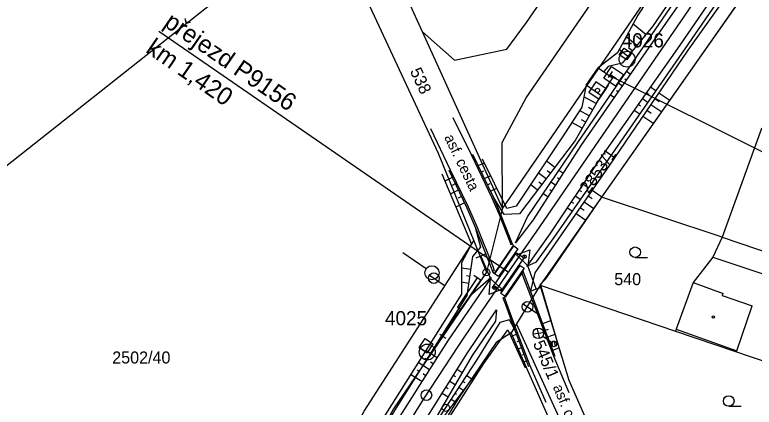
# Model space of a CAD drawing. Extents: x -558358 to -557517, y -1073786 to -1073189.
# Drawn here: x -558303.9 to -558199.4, y -1073559.5 to -1073504 of the extents above; entities that cross this region are included whole.
import ezdxf

# ---------------------------------------------------------------- set-up
doc = ezdxf.new("R2010")
doc.units = 0
for name, color, linetype in [('Body', 7, 'Continuous'), ('bubliny', 7, 'Continuous'), ('Hranice parcel', 7, 'Continuous'), ('Kolej', 7, 'Continuous'), ('Lomové body_cisla', 7, 'Continuous'), ('Lomové body_krizky', 7, 'Continuous'), ('nové prvky ZZ', 7, 'Continuous'), ('Návěst místo trati', 7, 'Continuous'), ('Návěst ostatní', 7, 'Continuous'), ('Parcelní čísla', 7, 'Continuous'), ('Plot - zábradlí', 7, 'Continuous'), ('Přejezd - štěrkové lože', 7, 'Continuous'), ('Sdělovací objekt', 7, 'Continuous'), ('Sonda - šrafa - vrstevnice', 7, 'Continuous'), ('Svazek obcí údolí Desné', 7, 'Continuous'), ('Svršek součást', 7, 'Continuous'), ('Vedení nerozlišené', 7, 'Continuous'), ('Vnitřní kresba', 7, 'Continuous'), ('Vrstva 1', 7, 'Continuous'), ('Vrstva 28', 7, 'Continuous'), ('Vrstva 60', 7, 'Continuous'), ('Značky budov', 7, 'Continuous'), ('Značky kultur', 7, 'Continuous'), ('ŽKN drážní hranice', 7, 'Continuous')]:
    doc.layers.add(name, color=color, linetype=linetype)

msp = doc.modelspace()

# ---------------------------------------------------------------- linework, layer by layer
at = {"layer": 'Body'}
for p, q in [((-558217.8, -1073508.74), (-558216.76, -1073509.48)), ((-558217.4, -1073510.42), (-558218.48, -1073509.68)), ((-558246.72, -1073551.05), (-558245.6, -1073551.8))]:
    msp.add_line(p, q, dxfattribs=at)
for points in [[(-558216.76, -1073509.48), (-558217.4, -1073510.42), (-558218.48, -1073509.68), (-558217.8, -1073508.74), (-558216.76, -1073509.48)], [(-558218.48, -1073509.68), (-558218.48, -1073509.68), (-558217.8, -1073508.74), (-558217.8, -1073508.74)], [(-558244.79, -1073550.55), (-558245.6, -1073551.8), (-558246.72, -1073551.05), (-558245.88, -1073549.79), (-558244.79, -1073550.55)], [(-558246.72, -1073551.05), (-558246.72, -1073551.05), (-558245.88, -1073549.79)]]:
    msp.add_lwpolyline(points, dxfattribs=at)
at = {"layer": 'bubliny'}
for points in [[(-558241.97, -1073518.56), (-558239.36, -1073523.89), (-558236.46, -1073529.9), (-558235.46, -1073532.27), (-558233.99, -1073535.97), (-558233.78, -1073536.52), (-558233.57, -1073536.45), (-558233.47, -1073536.63), (-558236.17, -1073540.59), (-558236.37, -1073540.25)], [(-558245.14, -1073520.13), (-558242.35, -1073525.93), (-558239.8, -1073531.2), (-558238.6, -1073533.96), (-558236.31, -1073539.72), (-558236.16, -1073540.16)], [(-558233.57, -1073536.45), (-558235.25, -1073532.18), (-558236.26, -1073529.8), (-558239.16, -1073523.77)], [(-558242.57, -1073526.01), (-558240.01, -1073531.3), (-558238.82, -1073534.05), (-558236.37, -1073540.25), (-558236.16, -1073540.16)], [(-558227.51, -1073552.32), (-558229.58, -1073546.84), (-558231, -1073543.03), (-558232.06, -1073540.27), (-558232.25, -1073540.54), (-558234.54, -1073543.87), (-558234.71, -1073543.93), (-558234.92, -1073544.01), (-558234.56, -1073544.97), (-558233.31, -1073548.35), (-558231.29, -1073553.74)], [(-558232.25, -1073540.54), (-558231.98, -1073541.2), (-558229.8, -1073546.93), (-558227.73, -1073552.39), (-558225.6, -1073557.4)], [(-558228.82, -1073558.84), (-558231.07, -1073553.66), (-558233.11, -1073548.21), (-558234.34, -1073544.89), (-558234.71, -1073543.93)]]:
    msp.add_lwpolyline(points, dxfattribs=at)
at = {"layer": 'Hranice parcel'}
for p, q in [((-558325.69, -1073541.72), (-558259.89, -1073489.61)), ((-558246.29, -1073506.44), (-558252.58, -1073492.61)), ((-558234.96, -1073531.36), (-558246.29, -1073506.44)), ((-558234.96, -1073531.36), (-558235.03, -1073522.1)), ((-558203.93, -1073535.45), (-558220.99, -1073529.81)), ((-558229.66, -1073542.22), (-558210.55, -1073548.74)), ((-558218.9, -1073578.68), (-558232.98, -1073547.69)), ((-558220.27, -1073579.28), (-558233.76, -1073548.97)), ((-558210.55, -1073548.74), (-558179.99, -1073559.12))]:
    msp.add_line(p, q, dxfattribs=at)
for points in [[(-558246.29, -1073506.44), (-558241.75, -1073510.46), (-558234.37, -1073508.88), (-558231.59, -1073505.15), (-558202.26, -1073462.53)], [(-558235.03, -1073522.1), (-558231.61, -1073515.78), (-558197.28, -1073465.89)], [(-558259.89, -1073489.61), (-558244.04, -1073523.6), (-558239.03, -1073535.96)], [(-558195.03, -1073520.62), (-558198.39, -1073520.09), (-558203.93, -1073535.45)], [(-558203.93, -1073535.45), (-558205.25, -1073538.29), (-558208.03, -1073541.86), (-558210.44, -1073548.45), (-558210.55, -1073548.74)], [(-558203.93, -1073535.45), (-558199.11, -1073537.11), (-558193.35, -1073539.1), (-558189.69, -1073540.36), (-558187.24, -1073541.19), (-558177.37, -1073544.49)], [(-558219.67, -1073569.09), (-558225.55, -1073555.71), (-558229.66, -1073542.22)]]:
    msp.add_lwpolyline(points, dxfattribs=at)
at = {"layer": 'Kolej'}
for points in [[(-558222.5, -1073523.52), (-558211.35, -1073507.26), (-558189.16, -1073474.89), (-558177.86, -1073458.42), (-558166.63, -1073442.09)], [(-558250.41, -1073565.28), (-558246.06, -1073558.3), (-558241.22, -1073550.9), (-558238.65, -1073547.06), (-558235.71, -1073542.74), (-558232.47, -1073538.02), (-558229.71, -1073534.01), (-558222.5, -1073523.52)]]:
    msp.add_lwpolyline(points, dxfattribs=at)
at = {"layer": 'Lomové body_cisla'}
for p, q in [((-558229.71, -1073549.76), (-558230.08, -1073548.32)), ((-558230.65, -1073549.14), (-558229.17, -1073548.94)), ((-558229.29, -1073549.47), (-558228.05, -1073550.31)), ((-558227.88, -1073550.9), (-558228, -1073550.25)), ((-558227.48, -1073550.85), (-558227.61, -1073550.16))]:
    msp.add_line(p, q, dxfattribs=at)
msp.add_lwpolyline([(-558221.47, -1073511.54), (-558219.41, -1073512.95), (-558221.09, -1073515.43), (-558223.16, -1073514)], close=True, dxfattribs=at)
for centre, radius in [((-558229.91, -1073549.05), 0.749), ((-558227.72, -1073550.54), 0.4), ((-558227.72, -1073550.54), 0.4)]:
    msp.add_circle(centre, radius, dxfattribs=at)
at = {"layer": 'Lomové body_krizky'}
msp.add_line((-558247.8, -1073566.83), (-558237.59, -1073553.32), dxfattribs=at)
for points in [[(-558160.27, -1073422.61), (-558170.92, -1073439.28), (-558182.07, -1073455.63), (-558193.45, -1073472.04), (-558204.95, -1073487.53), (-558215.83, -1073504.11), (-558218.74, -1073509.41), (-558221.47, -1073511.54)], [(-558158.61, -1073423.97), (-558169.15, -1073440.42), (-558180.26, -1073456.88), (-558191.27, -1073472.78), (-558202.46, -1073489.11), (-558213.8, -1073505.71), (-558218.06, -1073510.9), (-558220.02, -1073511.36), (-558220.66, -1073512.06)], [(-558152.7, -1073428.17), (-558163.49, -1073444.26), (-558174.92, -1073460.4), (-558186.51, -1073476.58), (-558197.24, -1073492.86), (-558208.77, -1073509.05), (-558219.85, -1073525.27), (-558227.1, -1073535.75), (-558230.39, -1073540.52), (-558231, -1073543.03)], [(-558223.16, -1073514), (-558223.75, -1073517.08), (-558226.14, -1073520.73), (-558233.06, -1073531.07), (-558234.34, -1073531.39), (-558237.78, -1073524.45)], [(-558221.09, -1073515.43), (-558224.69, -1073521.8), (-558232.56, -1073532.17), (-558234.74, -1073532.28), (-558236.26, -1073529.8)], [(-558243.55, -1073526.52), (-558241.09, -1073532.31), (-558239.34, -1073536.46), (-558240.77, -1073539.1), (-558240.78, -1073543.51), (-558244.12, -1073548.8), (-558253.49, -1073563.6), (-558259.69, -1073574.14), (-558265.34, -1073584.72), (-558270.8, -1073595.81), (-558275.48, -1073606.81), (-558278.77, -1073618.5)], [(-558238.82, -1073534.05), (-558238.07, -1073536.86), (-558239.2, -1073538.21), (-558240, -1073543.71), (-558243.46, -1073549.18), (-558252.76, -1073564.02), (-558258.92, -1073574.47), (-558264.72, -1073585.09), (-558269.64, -1073596.42), (-558274.5, -1073607.3), (-558278.77, -1073618.5)], [(-558233.31, -1073548.35), (-558233.96, -1073547.13), (-558235.35, -1073547.54), (-558238.57, -1073552.68), (-558247.8, -1073566.83)]]:
    msp.add_lwpolyline(points, dxfattribs=at)
at = {"layer": 'nové prvky ZZ'}
msp.add_line((-558233.36, -1073548.08), (-558233.26, -1073548.14), dxfattribs=at)
at = {"layer": 'Návěst místo trati'}
for p, q in [((-558243.83, -1073549.16), (-558242.99, -1073549.72)), ((-558243.69, -1073549.86), (-558243.14, -1073549.02))]:
    msp.add_line(p, q, dxfattribs=at)
for centre, radius in [((-558245.72, -1073557.78), 0.75), ((-558242.97, -1073559.57), 0.5), ((-558242.97, -1073559.57), 0.5)]:
    msp.add_circle(centre, radius, dxfattribs=at)
at = {"layer": 'Návěst ostatní'}
for p, q in [((-558238.54, -1073541.21), (-558241.35, -1073545.35)), ((-558238.54, -1073541.21), (-558239.04, -1073540.87)), ((-558238.05, -1073541.55), (-558238.54, -1073541.21)), ((-558240.85, -1073545.68), (-558238.05, -1073541.55)), ((-558241.35, -1073545.35), (-558240.85, -1073545.68))]:
    msp.add_line(p, q, dxfattribs=at)
at = {"layer": 'Plot - zábradlí'}
for points in [[(-558226.6, -1073552.39), (-558229.62, -1073542.12), (-558228.84, -1073541.34), (-558220.94, -1073529.81), (-558210.66, -1073515.21), (-558195.56, -1073493.62), (-558184.31, -1073477.57), (-558177.73, -1073468.27), (-558161.67, -1073445.55), (-558150.68, -1073429.95)], [(-558267.89, -1073660.39), (-558276.96, -1073659.75), (-558281.76, -1073647.44), (-558277.17, -1073632.83), (-558274.66, -1073624.85), (-558270.86, -1073615.23), (-558262.75, -1073596.69), (-558258.8, -1073588.16), (-558252.1, -1073576.95), (-558245.86, -1073566.23), (-558237.59, -1073553.32), (-558234.22, -1073548.55), (-558231.78, -1073553.91)]]:
    msp.add_lwpolyline(points, dxfattribs=at)
at = {"layer": 'Přejezd - štěrkové lože'}
for p, q in [((-558283.53, -1073506.38), (-558234.1, -1073540.39)), ((-558216.93, -1073512.45), (-558217.46, -1073512.08)), ((-558218.07, -1073514.09), (-558218.59, -1073513.73)), ((-558217.5, -1073513.27), (-558217.71, -1073513.12)), ((-558218.64, -1073514.91), (-558218.85, -1073514.77)), ((-558214.64, -1073515.05), (-558214.32, -1073515.28)), ((-558214.06, -1073514.23), (-558213.26, -1073514.8)), ((-558219.21, -1073515.73), (-558219.72, -1073515.38)), ((-558215.21, -1073515.87), (-558214.4, -1073516.44)), ((-558215.79, -1073516.68), (-558215.46, -1073516.92)), ((-558216.37, -1073517.5), (-558215.54, -1073518.08)), ((-558226.43, -1073526.41), (-558226.99, -1073526.05)), ((-558226.96, -1073527.26), (-558227.2, -1073527.1)), ((-558227.5, -1073528.1), (-558228.12, -1073527.7)), ((-558223.59, -1073527.97), (-558222.78, -1073528.51)), ((-558228.58, -1073529.78), (-558229.24, -1073529.36)), ((-558228.04, -1073528.94), (-558228.3, -1073528.78)), ((-558224.7, -1073529.63), (-558223.92, -1073530.15)), ((-558224.15, -1073528.8), (-558223.83, -1073529.01)), ((-558225.25, -1073530.46), (-558224.95, -1073530.67)), ((-558225.81, -1073531.3), (-558225.07, -1073531.79)), ((-558233.4, -1073536.68), (-558236.1, -1073540.62)), ((-558237.3, -1073537.83), (-558238.73, -1073538.43)), ((-558231.97, -1073538.44), (-558231.75, -1073538)), ((-558234.61, -1073543.82), (-558231.9, -1073539.88)), ((-558236.03, -1073542.36), (-558236.22, -1073542.81)), ((-558230.94, -1073543.03), (-558229.47, -1073542.51)), ((-558244.21, -1073552.5), (-558245.16, -1073551.89)), ((-558245.29, -1073554.19), (-558246.22, -1073553.59)), ((-558244.75, -1073553.34), (-558245.12, -1073553.1)), ((-558245.83, -1073555.03), (-558246.2, -1073554.79)), ((-558241.36, -1073554.11), (-558240.65, -1073554.56)), ((-558246.37, -1073555.87), (-558247.29, -1073555.28)), ((-558242.42, -1073555.81), (-558241.65, -1073556.29)), ((-558241.89, -1073554.96), (-558241.59, -1073555.15)), ((-558242.95, -1073556.66), (-558242.63, -1073556.85)), ((-558243.48, -1073557.5), (-558242.66, -1073558.02))]:
    msp.add_line(p, q, dxfattribs=at)
for points in [[(-558233.12, -1073536.27), (-558231.44, -1073532.59), (-558224.31, -1073522.11), (-558213.32, -1073506.02), (-558201.98, -1073489.48), (-558190.68, -1073473.3), (-558179.76, -1073457.16), (-558168.65, -1073440.76), (-558157.79, -1073424.72)], [(-558157.06, -1073425.16), (-558168.03, -1073441.18), (-558179.14, -1073457.55), (-558190.46, -1073474.12), (-558201.29, -1073490), (-558212.69, -1073506.36), (-558223.92, -1073522.5), (-558230.65, -1073533.02), (-558233.12, -1073536.27)], [(-558154.33, -1073427.06), (-558164.84, -1073443.28), (-558176.23, -1073459.59), (-558187.79, -1073475.9), (-558198.67, -1073491.89), (-558209.91, -1073508.33), (-558221.19, -1073524.36), (-558228.27, -1073535), (-558231.51, -1073539.54)], [(-558231.51, -1073539.54), (-558230.18, -1073538.97), (-558227.65, -1073535.49), (-558220.31, -1073524.95), (-558209.15, -1073508.87), (-558197.9, -1073492.46), (-558187.04, -1073476.34), (-558175.63, -1073459.98), (-558164.25, -1073443.72), (-558153.52, -1073427.77)], [(-558230.2, -1073542.77), (-558231.37, -1073539.5), (-558232.98, -1073537.94), (-558231.1, -1073537.26), (-558231.37, -1073539.5)], [(-558238.02, -1073538.13), (-558236.68, -1073541.34), (-558235, -1073542.81), (-558236.84, -1073543.58), (-558236.68, -1073541.34)], [(-558236.57, -1073541.18), (-558242.63, -1073550.03), (-558251.8, -1073564.36), (-558258.08, -1073574.96), (-558263.68, -1073585.42), (-558268.89, -1073596.63), (-558273.56, -1073607.36), (-558277.84, -1073618.92), (-558281.55, -1073630.05), (-558284.86, -1073641.54), (-558287.93, -1073653.35), (-558290.36, -1073665.39), (-558292.44, -1073677.06), (-558293.84, -1073688.83), (-558294.98, -1073700.92), (-558295.5, -1073713.2), (-558295.65, -1073725.09), (-558295.34, -1073737.57), (-558294.51, -1073749.18), (-558292.85, -1073761.97)], [(-558236.57, -1073541.18), (-558239.57, -1073543.79), (-558243.46, -1073549.18)], [(-558289.76, -1073760.35), (-558291.17, -1073748.87), (-558292.01, -1073737.3), (-558292.42, -1073725.02), (-558292.29, -1073713.18), (-558291.76, -1073701.11), (-558290.62, -1073689.2), (-558289.11, -1073677.44), (-558287.17, -1073665.92), (-558284.76, -1073654.08), (-558281.79, -1073642.38), (-558278.31, -1073631.08), (-558274.71, -1073619.92), (-558270.32, -1073608.64), (-558265.7, -1073597.9), (-558260.51, -1073586.94), (-558255.05, -1073576.61), (-558248.93, -1073566.18), (-558239.9, -1073551.79), (-558235.83, -1073545.74)], [(-558235.83, -1073545.74), (-558235.98, -1073547.31), (-558239.26, -1073552.18), (-558247.8, -1073566.83), (-558254.24, -1073577.1), (-558259.62, -1073587.52), (-558264.88, -1073598.21), (-558269.46, -1073609.08), (-558273.88, -1073620.25), (-558277.7, -1073631.3), (-558281, -1073642.51), (-558283.78, -1073654.25)]]:
    msp.add_lwpolyline(points, dxfattribs=at)
for points in [[(-558236.1, -1073540.65), (-558233.39, -1073536.69), (-558232.81, -1073537.09), (-558235.52, -1073541.04)], [(-558233, -1073537.69), (-558231.96, -1073538.4), (-558235.2, -1073543.1), (-558236.24, -1073542.37)], [(-558235.2, -1073543.42), (-558232.48, -1073539.47), (-558231.91, -1073539.86), (-558234.63, -1073543.82)]]:
    msp.add_lwpolyline(points, close=True, dxfattribs=at)
for centre in [(-558231.86, -1073538.22), (-558236.13, -1073542.59)]:
    msp.add_circle(centre, 0.248, dxfattribs=at)
at = {"layer": 'Sdělovací objekt'}
for p, q in [((-558219.98, -1073512.89), (-558219.42, -1073512.06)), ((-558219.7, -1073512.47), (-558218.87, -1073513.04))]:
    msp.add_line(p, q, dxfattribs=at)
msp.add_lwpolyline([(-558220.67, -1073513.02), (-558219.55, -1073511.37), (-558217.89, -1073512.49), (-558219.02, -1073514.14), (-558220.67, -1073513.02)], dxfattribs=at)
at = {"layer": 'Sonda - šrafa - vrstevnice'}
for p, q in [((-558214.73, -1073506.83), (-558216.52, -1073505.37)), ((-558216, -1073508.38), (-558217.5, -1073507.15)), ((-558215.36, -1073507.61), (-558216.02, -1073507.07)), ((-558216.63, -1073509.15), (-558217.18, -1073508.71)), ((-558217.27, -1073509.93), (-558218.48, -1073508.93)), ((-558212.87, -1073515.06), (-558211.31, -1073516.13)), ((-558221.75, -1073516.6), (-558223.47, -1073515.63)), ((-558213.44, -1073515.89), (-558212.82, -1073516.31)), ((-558222.24, -1073517.47), (-558222.81, -1073517.15)), ((-558214, -1073516.71), (-558212.46, -1073517.76)), ((-558222.73, -1073518.34), (-558224.08, -1073517.58)), ((-558214.57, -1073517.54), (-558213.95, -1073517.96)), ((-558223.71, -1073520.08), (-558225.18, -1073519.26)), ((-558223.22, -1073519.21), (-558223.79, -1073518.9)), ((-558215.13, -1073518.36), (-558213.61, -1073519.4)), ((-558238.39, -1073525.36), (-558237.53, -1073524.95)), ((-558227.59, -1073525.63), (-558228.8, -1073524.7)), ((-558237.96, -1073526.26), (-558237.61, -1073526.1)), ((-558228.8, -1073527.22), (-558229.92, -1073526.37)), ((-558228.19, -1073526.42), (-558228.66, -1073526.07)), ((-558242.08, -1073527.02), (-558243.12, -1073527.53)), ((-558237.52, -1073527.17), (-558236.64, -1073526.74)), ((-558241.65, -1073527.93), (-558242.08, -1073528.14)), ((-558237.09, -1073528.07), (-558236.73, -1073527.9)), ((-558236.66, -1073528.97), (-558235.75, -1073528.53)), ((-558230.01, -1073528.81), (-558231.03, -1073528.03)), ((-558229.4, -1073528.02), (-558229.83, -1073527.69)), ((-558241.21, -1073528.82), (-558242.34, -1073529.37)), ((-558240.78, -1073529.73), (-558241.24, -1073529.95)), ((-558222.88, -1073529.64), (-558222.32, -1073530.02)), ((-558222.31, -1073528.82), (-558220.92, -1073529.78)), ((-558240.34, -1073530.63), (-558241.55, -1073531.21)), ((-558223.45, -1073530.46), (-558222.05, -1073531.43)), ((-558224.02, -1073531.28), (-558223.45, -1073531.67)), ((-558224.58, -1073532.1), (-558223.18, -1073533.08)), ((-558239.46, -1073540.01), (-558240.77, -1073539.82)), ((-558239.6, -1073541), (-558240.07, -1073540.94)), ((-558239.75, -1073541.99), (-558240.77, -1073541.84)), ((-558229.27, -1073547.67), (-558228.12, -1073547.23)), ((-558228.92, -1073548.6), (-558228.48, -1073548.44)), ((-558232.98, -1073549.21), (-558233.78, -1073549.51)), ((-558228.56, -1073549.54), (-558227.55, -1073549.15)), ((-558232.64, -1073550.15), (-558232.93, -1073550.26)), ((-558228.21, -1073550.47), (-558227.83, -1073550.33)), ((-558245.17, -1073551.9), (-558245.82, -1073551.49)), ((-558232.29, -1073551.08), (-558232.95, -1073551.33)), ((-558227.85, -1073551.41), (-558226.99, -1073551.08)), ((-558245.7, -1073552.75), (-558245.96, -1073552.58)), ((-558231.94, -1073552.02), (-558232.18, -1073552.11)), ((-558246.23, -1073553.59), (-558246.89, -1073553.18)), ((-558231.59, -1073552.96), (-558232.13, -1073553.16)), ((-558246.76, -1073554.44), (-558247.03, -1073554.27)), ((-558247.29, -1073555.29), (-558247.96, -1073554.86)), ((-558240.61, -1073555.81), (-558240.31, -1073556.01)), ((-558240.06, -1073554.97), (-558239.25, -1073555.51)), ((-558241.16, -1073556.65), (-558240.45, -1073557.11)), ((-558241.7, -1073557.49), (-558241.45, -1073557.66)), ((-558242.25, -1073558.32), (-558241.66, -1073558.71))]:
    msp.add_line(p, q, dxfattribs=at)
at = {"layer": 'Svazek obcí údolí Desné'}
for p, q in [((-558177.75, -1073468.29), (-558220.99, -1073529.81)), ((-558192.36, -1073469.21), (-558234.96, -1073531.36)), ((-558220.99, -1073529.81), (-558229.66, -1073542.22)), ((-558234.96, -1073531.36), (-558237.23, -1073540.41)), ((-558239.03, -1073535.96), (-558237.23, -1073540.41)), ((-558229.66, -1073542.22), (-558232.98, -1073547.69)), ((-558232.98, -1073547.69), (-558233.76, -1073548.97))]:
    msp.add_line(p, q, dxfattribs=at)
for points in [[(-558286.79, -1073633.11), (-558279.73, -1073611.9), (-558267.63, -1073584.34), (-558254.51, -1073560.06), (-558239.03, -1073535.96)], [(-558237.23, -1073540.41), (-558250.35, -1073559.71), (-558264.4, -1073584.99), (-558277.08, -1073613.49), (-558283.33, -1073632.3), (-558290.3, -1073658.29), (-558296.01, -1073700.28), (-558297.13, -1073716.84), (-558297.21, -1073758.56)], [(-558233.76, -1073548.97), (-558235.85, -1073550.36), (-558241.19, -1073558.21), (-558248.9, -1073570.88), (-558258.93, -1073588.36)]]:
    msp.add_lwpolyline(points, dxfattribs=at)
at = {"layer": 'Svršek součást'}
for p, q in [((-558221.79, -1073513.5), (-558222.78, -1073514.97)), ((-558220.32, -1073514.5), (-558221.79, -1073513.5)), ((-558221.65, -1073516.45), (-558219.99, -1073514.01)), ((-558222.78, -1073514.97), (-558221.31, -1073515.96)), ((-558221.31, -1073515.96), (-558220.32, -1073514.5))]:
    msp.add_line(p, q, dxfattribs=at)
msp.add_circle((-558221.55, -1073514.73), 0.296, dxfattribs=at)
at = {"layer": 'Vedení nerozlišené'}
for p, q in [((-558245.77, -1073539.92), (-558249.07, -1073537.67)), ((-558245.29, -1073540.83), (-558243.22, -1073542.24)), ((-558244.94, -1073540.49), (-558244.94, -1073540.49)), ((-558232.06, -1073544.88), (-558229.99, -1073546.28))]:
    msp.add_line(p, q, dxfattribs=at)
for centre, radius in [((-558244.94, -1073540.49), 1), ((-558244.67, -1073541.26), 0.75), ((-558231.44, -1073545.3), 0.75)]:
    msp.add_circle(centre, radius, dxfattribs=at)
at = {"layer": 'Vnitřní kresba'}
for p, q in [((-558205.25, -1073538.29), (-558189.93, -1073543.4)), ((-558208.03, -1073541.86), (-558203.81, -1073543.44)), ((-558203.92, -1073543.72), (-558203.81, -1073543.44)), ((-558203.92, -1073543.72), (-558199.71, -1073545.18)), ((-558201.86, -1073551.5), (-558199.71, -1073545.18)), ((-558210.44, -1073548.45), (-558201.86, -1073551.5))]:
    msp.add_line(p, q, dxfattribs=at)
at = {"layer": 'Vrstva 28'}
msp.add_line((-558220.14, -1073512.46), (-557941.76, -1073651.48), dxfattribs=at)
at = {"layer": 'Vrstva 60'}
for p, q in [((-558217.37, -1073510.31), (-558217.37, -1073510.31)), ((-558217.37, -1073510.31), (-558217.37, -1073510.31)), ((-558245.6, -1073551.69), (-558245.6, -1073551.69)), ((-558245.6, -1073551.69), (-558245.6, -1073551.69))]:
    msp.add_line(p, q, dxfattribs=at)
for centre, radius in [((-558217.37, -1073510.31), 1.12), ((-558217.37, -1073510.31), 1.12), ((-558217.37, -1073510.31), 0.045), ((-558217.37, -1073510.31), 0.045), ((-558245.6, -1073551.69), 1.12), ((-558245.6, -1073551.69), 1.12), ((-558245.6, -1073551.69), 0.045), ((-558245.6, -1073551.69), 0.045)]:
    msp.add_circle(centre, radius, dxfattribs=at)
at = {"layer": 'Značky budov'}
msp.add_circle((-558205.18, -1073546.74), 0.175, dxfattribs=at)
at = {"layer": 'Značky kultur'}
for p, q in [((-558216.23, -1073538.34), (-558214.48, -1073538.34)), ((-558203.01, -1073559.36), (-558201.26, -1073559.36))]:
    msp.add_line(p, q, dxfattribs=at)
for centre in [(-558216.23, -1073537.59), (-558203.01, -1073558.61)]:
    msp.add_circle(centre, 0.75, dxfattribs=at)
at = {"layer": 'ŽKN drážní hranice'}
msp.add_line((-558237.31, -1073540.44), (-558237.21, -1073540.44), dxfattribs=at)
msp.add_circle((-558237.26, -1073540.44), 0.499, dxfattribs=at)

# ---------------------------------------------------------------- texts
at = {"layer": 'bubliny'}
for rotation, p in [(295.7563, (-558243.24, -1073521.35)), (292.4319, (-558227.88, -1073556.62))]:
    msp.add_text('asf. cesta', height=1.5, rotation=rotation, dxfattribs=at).set_placement(p)
at = {"layer": 'Parcelní čísla'}
for s, rotation, p in [('538', 295, (-558248.08, -1073512)), ('545/1', 293, (-558230.7, -1073550.47))]:
    msp.add_text(s, height=1.7, rotation=rotation, dxfattribs=at).set_placement(p)
for s, p in [('540', (-558219.18, -1073542.24)), ('2502/40', (-558290.1, -1073553.31))]:
    msp.add_text(s, height=1.7, dxfattribs=at).set_placement(p)
at = {"layer": 'Přejezd - štěrkové lože'}
for s, p in [('přejezd P9156', (-558282.96, -1073505.56)), ('km 1,420', (-558285.51, -1073509.26))]:
    msp.add_text(s, height=2.5, rotation=325.4703, dxfattribs=at).set_placement(p)
at = {"layer": 'Vrstva 1'}
msp.add_text('2853/1', height=1.7, rotation=55, dxfattribs=at).set_placement((-558222.82, -1073529.41))
at = {"layer": 'Vrstva 60'}
for s, p in [('4026', (-558218.13, -1073508.65)), ('4025', (-558251.57, -1073547.91))]:
    msp.add_text(s, height=2, dxfattribs=at).set_placement(p)

doc.saveas('drawing.dxf')
